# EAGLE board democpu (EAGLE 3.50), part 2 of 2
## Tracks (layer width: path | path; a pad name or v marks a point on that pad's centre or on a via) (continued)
P26-1  (via drill 0.41 pad 0.61) (continued)
  Top 0.203: 22.23,21.59 22.54,22.54 22.86,22.86 28.57,22.86 28.89,22.54 28.89,22.23 32.38,22.23 v33.97,22.23 38.1,22.23 38.1,22.54 38.42,22.86 44.45,22.86 44.77,22.54 46.67,22.54 47.62,22.23 | v34.92,78.74 v66.67,78.74
  Route2 0.203: v33.97,22.23 33.66,22.54 33.66,41.59 34.29,41.91 33.66,42.23 33.66,43.18 33.34,43.5 33.34,43.81 33.02,44.13 33.02,74.29 33.97,74.29 34.29,74.61 34.29,78.74 v34.92,78.74
  Bottom 0.203: v66.67,78.74 66.67,73.66
P27-1  (via drill 0.41 pad 0.61)
  Top 0.203: v30.8,20.32 28.57,20.32 28.57,20 28.26,19.69 18.41,19.69 18.41,21.59 | v35.56,78.1 v61.59,78.1
  Bottom 0.203: v30.8,20.32 32.7,20.32 32.7,26.35 33.02,26.67 33.02,39.69 33.34,40.01 34.61,40.01 34.61,40.64 34.92,40.96 35.56,40.96 35.56,42.23 35.24,42.55 35.24,42.86 34.92,43.18 34.92,44.13 34.29,44.45 34.92,44.77 34.92,67.94 35.24,68.26 35.24,69.22 35.56,69.53 v35.56,78.1 | v61.59,78.1 61.59,73.66
P40-1  (via drill 0.41 pad 0.61)
  Top 0.203: v29.21,75.56 2.54,75.56 2.54,72.71 2.41,72.01
  Bottom 0.203: v29.21,75.56 29.21,72.39
P41-1  (via drill 0.41 pad 0.61)
  Top 0.203: v27.94,74.93 3.49,74.93 3.49,71.12 3.17,71.12 2.86,70.8 2.54,70.8 2.54,70.17 2.41,69.47
  Bottom 0.203: v27.94,74.93 27.94,72.07 28.26,71.75 28.26,71.44 28.57,71.12 28.57,70.17 29.21,69.85
P42-1
  Top 0.203: 2.41,66.93 2.54,67.63 3.49,67.63 3.81,67.94 3.81,70.17 4.13,70.49 4.45,70.49 4.76,70.8 5.4,70.8 5.71,71.12 11.75,71.12 12.06,71.44 12.06,74.29 21.91,74.29 22.23,73.98 22.23,73.66 24.45,73.66 24.77,73.34 26.04,73.34 26.35,73.03 26.67,72.39
P43-1  (via drill 0.41 pad 0.61)
  Top 0.203: v3.49,77.47 9.21,77.47 9.53,77.15 9.53,76.84 v24.13,76.84
  Bottom 0.203: v3.49,77.47 3.49,66.04 3.17,65.72 3.17,64.45 2.41,64.39 | v24.13,76.84 24.13,72.39
P44-1  (via drill 0.41 pad 0.61)
  Top 0.203: v24.13,63.5 13.65,63.5 13.34,63.18 4.76,63.18 4.45,62.87 4.13,62.87 3.81,62.55 2.54,62.55 2.41,61.85
  Bottom 0.203: v24.13,63.5 24.13,69.85
P45-1
  Route2 0.203: 2.41,59.31 3.17,59.37 3.17,59.69 3.49,60.01 4.13,60.01 4.13,60.33 4.45,60.33 4.76,60.64 11.43,60.64 11.43,73.98 11.75,74.29 21.59,74.29 21.59,72.39
P46-1  (via drill 0.41 pad 0.61)
  Top 0.203: v6.67,70.49 13.02,70.49 13.34,70.8 13.34,71.12 19.37,71.12 19.68,70.8 20,70.8 20.32,70.49 21.27,70.49 21.59,69.85
  Bottom 0.203: v6.67,70.49 6.67,62.23 6.35,61.91 6.35,60.64 4.76,60.64 4.45,60.33 4.13,60.33 4.13,60.01 3.81,60.01 3.49,59.69 3.49,58.42 3.17,58.1 3.17,56.83 2.41,56.77
P47-1  (via drill 0.41 pad 0.61)
  Top 0.203: v11.43,55.56 4.76,55.56 4.45,55.24 4.13,55.24 3.81,54.93 2.54,54.93 2.41,54.23
  Bottom 0.203: v11.43,55.56 11.43,71.44 11.75,71.75 15.56,71.75 15.88,71.44 15.88,71.12 18.41,71.12 18.41,72.07 19.05,72.39
P50-1
  Top 0.203: 4.95,69.47 5.4,68.9 13.34,68.9 13.65,68.58 14.29,68.58 14.61,68.26 14.92,68.26 14.92,67.94 15.24,67.63 15.24,66.67 15.56,66.67 15.88,66.36 15.88,66.04 16.83,66.04 17.14,65.72 17.46,65.72 17.78,65.41 18.1,65.41 18.41,65.09 18.73,65.09 18.73,64.13 40.96,64.13 41.27,63.82 41.27,63.5 42.23,63.5 42.55,63.18 42.86,63.18 43.18,62.87 44.13,62.87 44.45,62.23
P51-1  (via drill 0.41 pad 0.61)
  Top 0.203: v24.13,59.69 41.91,59.69
  Route15 0.203: v24.13,59.69 23.5,59.69 23.5,65.09 23.18,65.41 17.78,65.41 17.46,65.72 17.14,65.72 16.83,66.04 13.65,66.04 13.34,66.36 12.06,66.36 11.75,66.67 10.48,66.67 10.16,66.36 5.4,66.36 4.95,66.93
P52-1  (via drill 0.41 pad 0.61)
  Top 0.203: v20.32,62.87 20.32,62.23 40.32,62.23 40.64,61.91 40.64,60.96 42.23,60.96 42.55,60.64 42.86,60.64 43.18,60.33 44.13,60.33 44.45,59.69
  Route15 0.203: v20.32,62.87 17.78,62.87 17.46,63.18 17.14,63.18 16.83,63.5 13.65,63.5 13.34,63.82 5.4,63.82 4.95,64.39
P53-1  (via drill 0.41 pad 0.61)
  Top 0.203: v20.95,57.79 41.59,57.79 41.91,57.15
  Route15 0.203: v20.95,57.79 19.68,57.79 19.68,60.01 19.37,60.33 17.78,60.33 17.46,60.64 17.14,60.64 16.83,60.96 6.67,60.96 6.35,61.28 5.4,61.28 4.95,61.85
P54-1  (via drill 0.41 pad 0.61)
  Top 0.203: v18.41,58.42 42.23,58.42 42.55,58.1 42.86,58.1 43.18,57.79 44.13,57.79 44.45,57.15
  Route15 0.203: v18.41,58.42 9.53,58.42 9.21,58.74 5.4,58.74 4.95,59.31
P55-1
  Top 0.203: 4.95,56.77 5.4,56.2 13.34,56.2 13.65,55.88 16.83,55.88 17.14,55.56 18.1,55.56 18.41,55.24 41.59,55.24 41.91,54.61
P56-1  (via drill 0.41 pad 0.61)
  Top 0.203: v20.95,55.88 42.23,55.88 42.55,55.56 42.86,55.56 43.18,55.24 44.13,55.24 44.45,54.61
  Route15 0.203: v20.95,55.88 13.65,55.88 13.34,55.56 13.02,55.56 13.02,55.24 12.7,54.93 5.08,54.93 4.95,54.23
P57-1
  Top 0.203: 4.95,51.69 5.4,51.12 13.34,51.12 13.65,50.8 16.83,50.8 17.14,51.12 40.01,51.12 40.32,51.44 41.59,51.44 41.91,52.07
P66-1  (via drill 0.41 pad 0.61)
  Top 0.203: v36.83,49.21 20.32,49.21 20.32,46.67 20,46.35 17.78,46.35 17.46,46.04 17.14,46.04 16.83,45.72 13.65,45.72 13.34,45.4 4.13,45.4 4.13,45.72 3.81,46.04 2.86,46.04 2.41,46.61
  Route2 0.203: v36.83,49.21 37.47,49.21 37.47,66.99 37.78,67.31 40.01,67.31 40.01,68.9 40.32,69.22 41.27,69.22 41.27,69.53 41.91,69.85
P67-1  (via drill 0.41 pad 0.61)
  Top 0.203: v7.62,76.84 8.57,76.84 8.89,76.52 8.89,76.2 38.73,76.2 39.05,75.88 39.05,73.03 39.37,72.39
  Bottom 0.203: v7.62,76.84 7.62,49.21 6.99,49.21 6.67,48.9 6.67,45.4 4.76,45.4 4.45,45.09 4.13,45.09 3.81,44.77 3.81,44.13 3.17,44.13 2.41,44.07
P70-1  (via drill 0.41 pad 0.61)
  Top 0.203: v6.03,58.1 6.35,58.42 6.67,58.42 6.67,59.69 13.97,59.69
  Bottom 0.203: v6.03,58.1 6.03,50.8 5.71,50.8 5.4,50.48 5.4,49.53 4.95,49.15
P71-1  (via drill 0.41 pad 0.61)
  Top 0.203: v6.99,61.59 7.3,61.28 13.34,61.28 13.65,60.96 14.29,60.96 14.61,61.28 14.92,61.28 15.24,61.59 16.19,61.59 16.51,62.23
  Bottom 0.203: v6.99,61.59 6.99,59.37 6.67,59.05 6.67,49.53 6.35,49.53 6.03,49.21 6.03,48.26 5.71,47.94 5.71,46.67 4.95,46.61
P72-1  (via drill 0.41 pad 0.61)
  Top 0.203: v12.06,44.13 5.71,44.13 4.95,44.07
  Bottom 0.203: v12.06,44.13 12.06,54.29 12.38,54.61 12.7,54.61 12.7,60.01 13.02,60.33 13.02,61.59 13.34,61.91 13.97,62.23
P73-1  (via drill 0.41 pad 0.61)
  Top 0.203: v10.79,41.59 5.71,41.59 4.95,41.53 | v10.79,68.26 10.79,66.04 14.29,66.04 14.61,65.72 14.92,65.72 15.24,65.41 16.19,65.41 16.51,64.77
  Bottom 0.203: v10.79,41.59 v10.79,68.26
P74-1
  Route2 0.203: 4.95,38.99 5.71,39.05 9.84,39.05 9.84,57.15 10.16,57.47 10.16,57.79 12.06,57.79 12.06,64.13 12.38,64.45 13.34,64.45 13.97,64.77
P75-1  (via drill 0.41 pad 0.61)
  Top 0.203: v11.43,37.15 5.08,37.15 4.95,36.45
  Bottom 0.203: v11.43,37.15 11.43,54.61 11.75,54.93 12.06,54.93 12.06,65.72 12.38,66.04 15.88,66.04 15.88,66.99 16.51,67.31
P80-1  (via drill 0.41 pad 0.61)
  Top 0.203: v22.86,30.48 22.54,30.16 4.76,30.16 4.45,29.84 4.13,29.84 3.81,29.53 2.54,29.53 2.41,28.83 | v23.5,67.31 36.51,67.31 36.83,67.63 36.83,68.58 37.15,68.58 37.47,68.9 38.42,68.9 38.73,69.22 39.05,69.22 39.37,69.85
  Bottom 0.203: v22.86,30.48 22.86,44.77 23.18,45.09 23.18,46.04 23.5,46.35 v23.5,67.31
P81-1  (via drill 0.41 pad 0.61)
  Top 0.203: v23.5,29.21 11.43,29.21 11.43,28.57 11.11,28.57 10.79,28.26 6.67,28.26 6.35,27.94 5.71,27.94 5.4,27.62 4.76,27.62 4.45,27.3 4.13,27.3 3.81,26.99 2.54,26.99 2.41,26.29 | v28.26,67.94 35.24,67.94 35.56,68.26 35.56,71.75 36.51,71.75 36.83,72.39
  Route2 0.203: v23.5,29.21 23.5,39.69 23.81,40.01 24.13,40.01 24.13,40.32 24.45,40.64 25.08,40.64 25.08,40.96 25.4,41.27 25.4,44.77 25.72,45.09 25.72,45.4 26.04,45.72 26.04,67.63 26.35,67.94 v28.26,67.94
P82-1  (via drill 0.41 pad 0.61)
  Top 0.203: v17.78,24.77 11.11,24.77 10.79,25.08 4.76,25.08 4.45,24.77 4.13,24.77 3.81,24.45 2.54,24.45 2.41,23.75 | v18.41,47.62 18.41,49.85 v36.2,49.85
  Bottom 0.203: v17.78,24.77 17.78,44.77 18.1,45.09 18.1,45.4 18.41,45.72 v18.41,47.62 | v36.2,49.85 36.83,49.85 36.83,69.85
P83-1  (via drill 0.41 pad 0.61)
  Top 0.203: v21.59,19.05 15.24,19.05 15.24,19.69 14.92,19.69 14.61,20 4.13,20 4.13,20.32 3.81,20.64 2.86,20.64 2.41,21.21 | v22.86,74.29 33.66,74.29 33.97,73.98 33.97,73.03 34.29,72.39
  Route2 0.203: v21.59,19.05 21.59,25.4 21.27,25.72 20.95,25.72 20.95,31.75 21.27,32.07 22.86,32.07 v22.86,74.29
PDWN-1  (via drill 0.41 pad 0.61)
  Top 0.203: v53.02,26.67 49.53,26.67 49.21,26.35 46.67,26.35 45.72,26.42 44.77,26.35 43.81,26.35 43.18,26.04 | v53.02,33.66 51.44,33.66 | v49.53,81.28 v84.45,81.28
  Route2 0.203: v49.53,81.28 49.53,51.75 49.21,51.44 47.62,51.44 47.62,35.24 47.31,34.92 47.31,34.61 45.09,34.61 45.09,26.67 44.77,26.35 43.81,26.35 43.18,26.04
  Bottom 0.203: v53.02,26.67 v53.02,33.66 | v84.45,81.28 84.45,73.66
PSEN-1  (via drill 0.41 pad 0.61)
  Top 0.203: v92.08,50.8 84.45,50.8
  Bottom 0.203: v92.08,50.8 92.08,40.96 92.39,40.64 92.39,40.32 92.71,40.01 92.71,26.67 95.57,26.67 95.89,26.99 96.2,26.99 96.2,27.3 96.52,27.62 96.52,28.57 96.2,28.57 95.89,28.89 95.89,30.16 95.22,30.46
PSENM-1  (via drill 0.41 pad 0.61)
  Top 0.203: v46.99,71.44 47.94,71.44 48.26,71.12 51.44,71.12
  Route2 0.203: v46.99,71.44 46.67,71.44 46.35,71.12 46.35,53.34 40.32,53.34 40.01,53.02 40.01,46.99 39.05,46.99 39.05,46.67 38.73,46.35 38.73,45.72 38.42,45.4 38.42,45.09 38.1,44.77 38.1,43.81 37.78,43.81 37.47,43.5 37.47,42.23 36.83,41.91
RD-1  (via drill 0.41 pad 0.61)
  Top 0.203: v75.56,59.69 53.34,59.69 53.34,60.01 53.02,60.33 51.75,60.33 51.44,60.96 | v74.93,44.45 84.77,44.45 85.09,44.13 86.04,44.13 86.36,43.81 v93.34,43.81
  Bottom 0.203: v75.56,59.69 75.56,45.4 75.25,45.09 75.25,44.77 v74.93,44.45 | v93.34,43.81 93.34,40.96 93.66,40.64 93.98,40.64 93.98,39.69 93.66,39.37 93.34,39.37 93.34,28.57 93.66,28.26 94.61,28.26 95.22,27.91
RDM-1  (via drill 0.41 pad 0.61)
  Top 0.203: v78.11,13.34 75.56,13.34 | 42.55,14.61 v40.96,14.61 | v55.88,14.61 57.78,14.61
  Route15 0.203: v40.96,14.61 v55.88,14.61 66.04,14.61 66.04,14.29 66.36,13.97 78.11,13.97 v78.11,13.34
  Bottom 0.203: v78.11,13.34 78.11,10.16 78.42,9.84 79.38,9.84 80.01,9.53
RDP-1
  Route15 0.203: 13.97,49.53 14.29,50.16 15.56,50.16 15.88,50.48 15.88,50.8 16.83,50.8 17.14,51.12 17.46,51.12 17.78,51.44 39.69,51.44 40.01,51.75 40.01,60.96 44.77,60.96 45.09,61.28 45.4,61.28 45.72,61.59 46.04,61.59 46.35,61.91 46.35,66.04 51.44,66.04
RDR-1  (via drill 0.41 pad 0.61)
  Route2 0.203: v75.25,20.96 75.25,40.01 75.56,40.32 75.56,46.04 75.88,46.35 75.88,46.67 76.2,46.99 76.2,66.36 76.52,66.67 78.42,66.67 78.74,66.99 78.74,68.26 79.38,68.58
  Route15 0.203: v75.25,20.96 62.55,20.96 62.23,20.64 59.05,20.64 58.74,20.96 30.48,20.96 30.16,20.64 6.35,20.64 6.03,20.32 5.71,20.32 5.4,20 4.76,20 4.45,19.69 4.13,19.69 3.81,19.37 3.49,19.37 3.49,17.78 3.17,17.78 3.17,17.14 2.86,16.83 2.54,16.83 2.41,16.13
RDRM-1  (via drill 0.41 pad 0.61)
  Top 0.203: v30.48,13.97 28.57,13.97 28.57,13.65 28.26,13.34 26.67,13.34 | v77.15,34.61 76.52,34.61 75.56,34.54
  Route15 0.203: v30.48,13.97 30.8,13.65 37.47,13.65 37.78,13.34 77.15,13.34 77.47,13.02 77.47,12.7 79.06,12.7 79.38,13.02 79.38,13.34 v81.92,13.34
  Bottom 0.203: v81.92,13.34 81.92,33.97 81.6,34.29 79.38,34.29 79.38,34.61 | 79.38,34.61 79.38,40.64 | 79.38,34.61 v77.15,34.61
RES-1  (via drill 0.41 pad 0.61)
  Top 0.203: 57.15,32.39 60.64,32.39 60.96,32.07 61.59,32.07 61.59,31.12 64.14,31.12 66.67,31.12 66.67,29.21 60.96,29.21 60.64,28.89 60.64,28.57 57.15,28.57 51.44,28.57 v48.26,28.57 | v19.05,53.34 v48.26,53.34
  Bottom 0.203: v48.26,53.34 v48.26,28.57 | v19.05,53.34 19.05,69.85
RLCA-1  (via drill 0.41 pad 0.61)
  Top 0.203: U10. 51.12,40.01 51.12,38.73 47.31,38.73 46.99,38.42 46.99,37.15 46.67,37.15 45.72,37.08
  Route15 0.203: v51.44,36.2 78.42,36.2 78.74,36.51 82.23,36.51 82.55,36.2 87.31,36.2 87.63,36.51 91.44,36.51 91.76,36.2 94.93,36.2 95.22,35.53
  Bottom 0.203: U10. v51.44,36.2
RSI-1  (via drill 0.41 pad 0.61)
  Top 0.203: 51.44,32.39 v53.66,32.39 | 48.9,37.08 49.85,37.15 v53.66,37.15 53.66,37.78 53.98,38.1 v92.08,38.1
  Bottom 0.203: v53.66,32.39 v53.66,37.15 | v92.08,38.1 92.08,23.18 94.61,23.18 95.22,22.84
RSO-1  (via drill 0.41 pad 0.61)
  Top 0.203: 95.22,17.76 94.93,18.41 91.12,18.41 90.81,18.73 90.81,19.69 87.63,19.69
  Route15 0.203: v32.38,26.99 32.38,22.86 36.51,22.86 36.83,22.54 36.83,22.23 74.93,22.23 75.25,21.91 75.25,21.59 79.06,21.59 79.38,21.27 79.38,20.96 80.33,20.96 80.64,20.64 80.96,20.64 81.28,20.32 87.31,20.32 87.63,19.69
  Bottom 0.203: v32.38,26.99 32.38,40.01 32.7,40.32 32.7,41.27 33.02,41.59 33.02,45.09 33.34,45.09 33.66,45.4 33.66,69.53 34.29,69.85
RX0-1  (via drill 0.41 pad 0.61)
  Top 0.203: v40.64,59.05 16.83,59.05 16.51,59.69
  Route15 0.203: v40.64,59.05 40.96,58.74 41.27,58.74 41.59,58.42 49.21,58.42 49.53,58.74 49.53,62.23 84.77,62.23 85.09,61.91 85.41,61.91 85.72,61.59 93.03,61.59 93.34,61.28 93.34,59.37 v94.3,59.37
  Bottom 0.203: v94.3,59.37 93.98,59.05 93.98,55.56 94.3,55.24 94.3,53.98 94.61,53.66 95.22,53.31
RX1-1  (via drill 0.41 pad 0.61)
  Top 0.203: v88.27,59.69 78.42,59.69 78.42,60.33 78.11,60.64 77.47,60.64 77.47,60.96 77.15,61.28 58.42,61.28 58.1,61.59 57.78,61.59 57.47,61.91 57.15,61.91 56.83,62.23 50.8,62.23 50.8,62.55 50.48,62.87 46.35,62.87 46.04,63.18 45.09,63.18 44.77,63.5 43.81,63.5 43.81,63.82 43.5,64.13 42.23,64.13 41.91,64.77 | v88.27,52.7 88.27,52.07 92.39,52.07 92.71,51.75 92.71,48.26 94.61,48.26 95.22,48.23
  Bottom 0.203: v88.27,59.69 v88.27,52.7
S$1
  Top 0.203: D4. 32.38,78.1
  Bottom 0.203: 32.38,78.1 32.38,80.65
S$2
  Top 0.203: 13.97,69.85 14.29,69.22 15.56,69.22 15.88,68.9 15.88,68.58 16.83,68.58 17.14,68.26 17.46,68.26 17.78,67.94 26.04,67.94 26.35,68.26 26.35,69.22 26.67,69.85 26.99,70.49 27.94,70.49 28.26,70.8 28.57,70.8 28.89,71.12 29.84,71.12 29.84,71.44 30.16,71.75 31.43,71.75 31.75,72.39
S$3  (via drill 0.41 pad 0.61)
  Top 0.203: 80.64,32.7 80.64,32.07 80.96,32.07 R9. | 80.64,32.7 80.64,33.02 80.33,33.34 79.69,33.34 79.69,33.97 R8. | 80.64,32.7 v84.45,32.7
  Bottom 0.203: 81.92,43.18 82.55,42.86 82.55,41.59 82.87,41.27 83.82,41.27 83.82,40.96 84.45,40.64 v84.45,32.7
SENS-1
  Top 0.203: 35.56,31.12 43.18,31.12
  Route15 0.203: 95.22,20.3 94.61,20.32 91.76,20.32 91.44,20.64 91.44,29.84 46.35,29.84 46.04,30.16 46.04,31.12 43.18,31.12
STD-1  (via drill 0.41 pad 0.61)
  Top 0.203: 80.01,27.3 76.83,27.3 76.52,27.62 73.66,27.62 73.34,27.94 73.34,28.26 72.39,28.83 | v38.1,57.15 16.51,57.15
  Route15 0.203: v38.1,24.45 38.42,24.77 43.5,24.77 43.81,25.08 50.8,25.08 51.12,25.4 51.44,25.4 51.44,26.04 76.52,26.04 76.83,26.35 76.83,27.3 80.01,27.3
  Bottom 0.203: v38.1,24.45 v38.1,57.15
T0-1
  Top 0.203: 2.41,51.69 2.54,52.39 3.81,52.39 4.13,52.7 4.45,52.7 4.76,53.02 13.34,53.02 13.65,53.34 14.29,53.34 14.61,53.66 14.92,53.66 15.24,53.98 16.19,53.98 16.51,54.61
T2-1
  Top 0.203: 2.41,49.15 2.86,48.58 3.81,48.58 4.13,48.26 4.13,47.94 13.34,47.94 13.65,48.26 14.29,48.26 14.61,48.58 14.92,48.58 15.24,48.9 16.19,48.9 16.51,49.53
TX1-1  (via drill 0.41 pad 0.61)
  Top 0.203: v60.33,50.8 76.52,50.8 76.83,50.48 76.83,49.53 82.23,49.53 82.55,49.21 82.87,49.21 82.87,48.9 83.19,48.58 83.19,47.62 83.5,47.62 83.82,47.31 83.82,46.99 84.77,46.99 85.09,46.67 86.04,46.67 86.36,46.35 94.93,46.35 95.22,45.7
  Route15 0.203: v59.69,69.85 47.31,69.85 47.31,68.26 46.99,68.26 46.67,67.94 44.77,67.94 44.45,67.31
  Bottom 0.203: 95.22,45.7 94.61,46.04 94.61,46.99 94.3,47.31 94.3,47.62 93.98,47.94 93.98,48.58 94.3,48.9 94.3,50.16 94.61,50.48 95.22,50.77 | v59.69,69.85 60.01,69.53 60.01,69.22 60.33,68.9 v60.33,50.8
VB  (via drill 0.41 pad 0.61)
  Top 0.203: 97.77,73.63 97.47,73.03 96.2,73.03 95.89,72.71 95.89,72.39 81.6,72.39 81.28,72.07 80.96,72.07 80.96,71.75 80.64,71.44 80.64,70.49 80.33,70.49 80.01,70.17 80.01,69.85 79.06,69.85 78.74,69.53 78.42,69.53 78.11,69.22 77.15,69.22 76.83,68.58 | 79.38,55.88 56.52,55.88 | 69.22,45.72 69.53,46.35 69.53,47.62 76.2,47.62 76.52,47.31 76.52,46.35 76.83,45.72 | v85.72,3.49 83.82,3.49 C3. | v37.15,3.49 36.2,3.49 C1. | v37.15,21.59 38.73,21.59 39.05,21.91 39.05,22.23 U6. 44.13,22.23 44.45,21.91 44.45,21.59 53.98,21.59 54.29,21.91 54.29,22.23 U5. 61.28,22.23 61.28,22.54 61.59,22.86 75.88,22.86 | v49.21,3.49 50.48,3.49 C2. | 75.88,22.86 78.11,22.86 78.42,23.18 79.38,23.18 79.69,23.5 80.64,23.5 80.64,23.18 80.96,22.86 87.31,22.86 87.63,22.23 | 75.88,22.86 v75.88,22.23
  Bottom 0.203: 69.22,45.72 69.22,68.58 | 57.47,55.24 57.47,53.98 57.78,53.66 57.78,48.58 57.15,48.58 56.52,48.26 | 57.47,55.24 57.15,55.56 56.52,55.88 | 57.47,55.24 57.47,57.79 57.78,58.1 57.78,65.72 57.15,65.72 56.52,66.04 | 77.47,55.24 77.47,46.04 76.83,45.72 76.2,45.4 76.2,44.13 75.88,43.81 75.56,43.81 75.56,22.54 v75.88,22.23 | 77.47,55.24 77.79,55.56 78.74,55.56 79.38,55.88 | 77.47,55.24 77.15,55.24 76.83,55.56 76.83,68.58 | U7. 87.63,24.77 87.63,22.23 87,21.91 86.04,21.91 85.72,21.59 v85.72,3.49 | v37.15,21.59 v37.15,3.49 v49.21,3.49
VCC  (via drill 0.41 pad 0.61)
  Top 0.203: v70.8,25.08 71.12,25.4 71.44,25.4 R1. | v70.48,19.37 70.48,20.96 | v70.48,3.18 68.58,3.18 C7. | R2. 74.61,25.72 73.34,25.72 R1. | R5. 71.75,32.07 71.75,33.02 71.44,33.34 70.8,33.34 69.85,33.66 66.36,33.66 66.04,33.97 66.04,36.51 61.28,36.51 R11. 59.37,37.15 57.78,37.15 57.78,34.92 | R6. 74.61,31.43 73.34,31.43 R5. | 57.78,34.92 57.78,33.97 57.15,33.66 | U2. 43.81,33.97 44.77,33.97 R4. 46.67,33.97 47.94,33.97 R10. 49.85,34.61 50.16,34.92 57.78,34.92 | R3. 45.09,29.84 45.09,33.02 43.5,33.02 U2. | R1. 71.75,26.35 71.75,27.62 71.44,27.62 71.12,27.94 71.12,31.12 71.44,31.12 R5. | v20.95,23.18 20.95,21.59 | U8. v20.64,34.29 20.64,34.92 20.95,35.24 27.3,35.24 27.62,35.56 28.26,35.56 28.57,35.24 36.2,35.24 36.2,34.61 36.51,34.29 42.86,34.29 U2. | v20,3.18 20.64,3.18 C6.
  Bottom 0.203: v70.8,25.08 70.8,19.69 v70.48,19.37 v70.48,3.18 | 20.32,74.93 17.46,74.93 17.14,74.61 17.14,72.71 16.51,72.39 | 20.32,74.93 20.32,76.2 | 20.32,76.2 20.32,78.1 | 20.32,76.2 22.86,76.2 23.18,76.52 23.18,77.47 29.53,77.47 29.84,77.15 29.84,74.29 30.16,73.98 30.16,73.03 30.48,72.71 30.48,71.75 30.8,71.75 31.11,71.44 31.11,70.17 31.75,69.85 | 20.64,23.5 v20.95,23.18 | 20.64,23.5 v20.64,34.29 20.64,41.27 20.32,41.59 20.32,42.23 20.64,42.55 20.64,42.86 20.95,43.18 20.95,44.13 21.59,44.45 21.59,63.18 21.27,63.5 21.27,67.94 20.95,68.26 20.95,68.58 20.64,68.9 20.64,69.22 20.32,69.53 20.32,74.93 | v20,3.18 20.32,3.49 20.32,23.18 20.64,23.5
VM
  Bottom 0.203: 4.95,72.01 5.71,72.07 5.71,80.01 6.03,80.33 9.53,80.33 D1.
WR-1  (via drill 0.41 pad 0.61)
  Top 0.203: v83.5,54.29 82.55,54.29 82.23,54.61 55.88,54.61 55.88,54.29 55.56,53.98 54.29,53.98 53.98,53.34 | v90.17,25.4 94.61,25.4 95.22,25.38
  Route2 0.203: v83.5,54.29 83.82,54.29 84.14,54.61 87,54.61 87,50.48 87.31,50.16 88.27,50.16 88.27,35.24 88.58,34.92 90.17,34.92 v90.17,25.4
WRM-1  (via drill 0.41 pad 0.61)
  Top 0.203: 42.55,20.96 43.81,20.96 44.45,20.32 49.53,20.32 49.85,20.64 49.85,20.96 57.78,20.96 59.05,20.96 v59.37,21.27 | v59.37,27.3 57.15,27.3 | v90.81,29.21 90.81,29.53 90.49,29.84 79.69,29.84 79.69,31.12 78.74,31.5
  Route15 0.203: v59.37,27.3 76.2,27.3 76.52,27.62 76.52,28.26 79.38,28.26 79.69,28.57 79.69,29.21 v90.81,29.21
  Bottom 0.203: v59.37,21.27 v59.37,27.3 | 89.53,29.21 89.53,32.07 89.22,32.39 86.36,32.39 86.36,46.67 86.04,46.99 83.19,46.99 83.19,47.31 82.87,47.62 82.55,47.62 82.55,47.94 81.92,48.26 | 89.53,29.21 89.53,7.3 88.27,7.3 87.63,6.99 | v90.81,29.21 89.53,29.21
WRP-1  (via drill 0.41 pad 0.61)
  Top 0.203: v19.68,66.04 44.77,66.04 45.09,65.72 46.04,65.72 46.35,65.41 50.48,65.41 50.8,65.09 50.8,64.77 51.75,64.77 52.07,64.45 52.39,64.45 52.7,64.13 53.66,64.13 53.98,63.5
  Bottom 0.203: v19.68,66.04 19.68,52.39 17.14,52.39 16.51,52.07
WRR-1  (via drill 0.41 pad 0.61)
  Top 0.203: v9.53,19.37 6.99,19.37 6.99,15.56 6.67,15.56 6.35,15.24 5.71,15.24 5.4,14.92 4.76,14.92 4.45,14.61 4.13,14.61 3.81,14.29 2.54,14.29 2.41,13.59
  Route15 0.203: v9.53,68.26 9.53,68.9 13.34,68.9 13.65,68.58 16.83,68.58 17.14,68.26 17.46,68.26 17.78,67.94 26.99,67.94 27.3,67.63 27.3,66.04 44.77,66.04 45.09,66.36 45.4,66.36 45.72,66.67 46.04,66.67 46.35,66.99 46.35,67.31 51.75,67.31 52.07,66.99 52.39,66.99 52.7,66.67 53.66,66.67 53.98,66.04
  Bottom 0.203: v9.53,19.37 v9.53,68.26
WRRM-1  (via drill 0.41 pad 0.61)
  Top 0.203: v80.33,34.92 80.64,34.61 80.96,34.61 81.92,34.54
  Bottom 0.203: v80.33,34.92 80.64,35.24 80.64,43.81 80.33,43.81 80.01,44.13 80.01,45.4 79.38,45.72

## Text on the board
tPlace: LCC32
